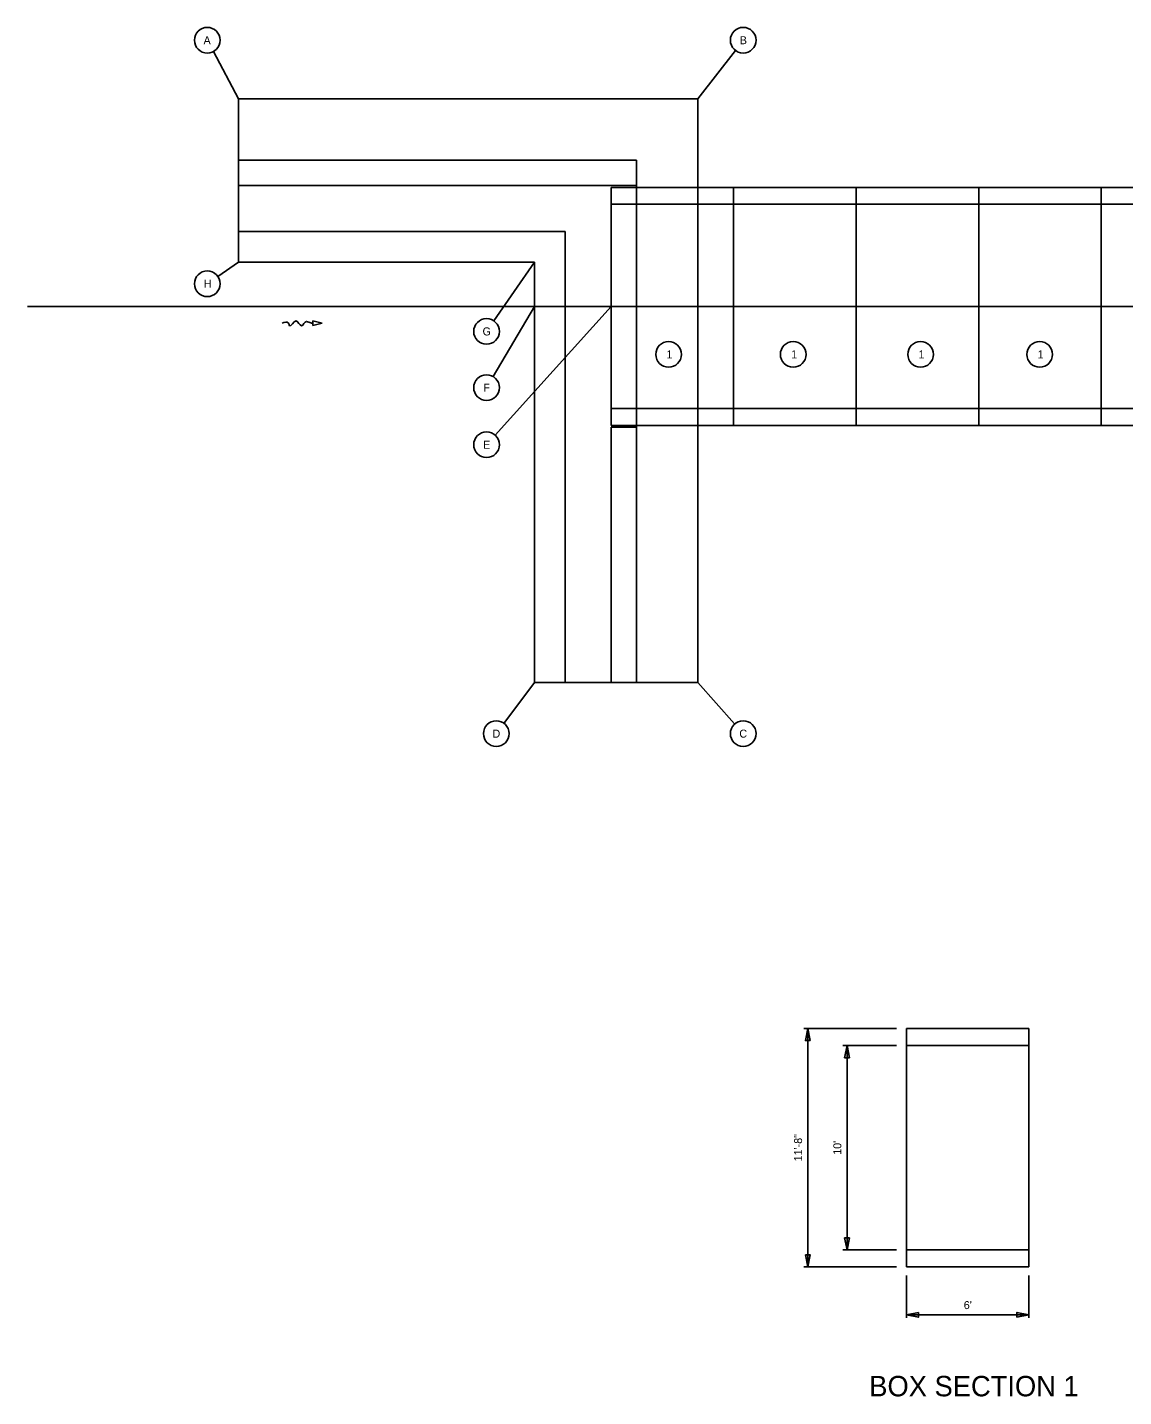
# Model space of a CAD drawing. Extents: x -324 to 238, y 0 to 489.
# Drawn here: x -323.5 to -189.4, y 297.6 to 465.2 of the extents above; entities that cross this region are included whole.
import ezdxf

# ---------------------------------------------------------------- set-up
doc = ezdxf.new("R2010")
doc.units = 0
for name, color, linetype in [('BR_P_Gen_Text', 7, 'Continuous'), ('DR_P_Culvert', 7, 'Continuous'), ('DR_P_Flow_Arrow', 7, 'Continuous'), ('GE_P_Alignment', 7, 'Continuous'), ('SH_Data', 7, 'Continuous'), ('TX_P_1', 7, 'Continuous')]:
    doc.layers.add(name, color=color, linetype=linetype)

msp = doc.modelspace()

# ---------------------------------------------------------------- linework, layer by layer
at = {"layer": 'BR_P_Gen_Text'}
for points in [[(-227.74, 341.17), (-228.33, 341.17), (-228.03, 342.64)], [(-222.94, 339.08), (-223.53, 339.08), (-223.23, 340.55)], [(-223.53, 317.02), (-222.94, 317.02), (-223.23, 315.55)], [(-228.33, 314.94), (-227.74, 314.94), (-228.03, 313.47)], [(-214.49, 307.9), (-214.49, 307.31), (-215.96, 307.6)], [(-202.43, 307.31), (-202.43, 307.9), (-200.96, 307.6)]]:
    msp.add_lwpolyline(points, close=True, dxfattribs=at)
at = {"layer": 'DR_P_Culvert'}
for p, q in [((-297.73, 436.46), (-297.73, 456.46)), ((-297.73, 456.46), (-241.48, 456.46)), ((-241.48, 456.46), (-241.48, 385.01)), ((-297.73, 448.96), (-248.98, 448.96)), ((-248.98, 416.26), (-248.98, 448.96)), ((-297.73, 445.84), (-252.11, 445.84)), ((-252.11, 445.84), (-248.98, 445.84)), ((-252.11, 416.46), (-252.11, 445.63)), ((-252.11, 445.63), (-94.61, 445.63)), ((-237.11, 416.46), (-237.11, 445.63)), ((-222.11, 416.46), (-222.11, 445.63)), ((-207.11, 416.46), (-207.11, 445.63)), ((-192.11, 416.46), (-192.11, 445.63)), ((-252.11, 443.55), (-94.61, 443.55)), ((-297.73, 440.21), (-257.73, 440.21)), ((-257.73, 440.21), (-257.73, 385.01)), ((-297.73, 436.46), (-261.48, 436.46)), ((-261.48, 436.46), (-261.48, 385.01)), ((-252.11, 418.55), (-94.61, 418.55)), ((-252.11, 416.46), (-94.61, 416.46)), ((-252.11, 416.26), (-248.98, 416.26)), ((-252.11, 416.26), (-252.11, 385.01)), ((-248.98, 416.26), (-248.98, 385.01)), ((-261.48, 385.01), (-241.48, 385.01)), ((-215.96, 342.64), (-200.96, 342.64)), ((-215.96, 313.47), (-215.96, 342.64)), ((-200.96, 313.47), (-200.96, 342.64)), ((-215.96, 340.55), (-200.96, 340.55)), ((-215.96, 315.55), (-200.96, 315.55)), ((-215.96, 313.47), (-200.96, 313.47))]:
    msp.add_line(p, q, dxfattribs=at)
at = {"layer": 'DR_P_Flow_Arrow'}
for p, q in [((-288.6, 429.3), (-287.48, 429)), ((-288.6, 428.7), (-288.6, 429.3)), ((-287.48, 429), (-288.6, 428.7))]:
    msp.add_line(p, q, dxfattribs=at)
msp.add_spline([(-288.6, 429), (-288.64, 429), (-289.1, 429.11), (-289.39, 429.21), (-289.99, 428.69), (-290.67, 429.27), (-291.45, 428.69), (-291.61, 429), (-292.38, 429)], degree=3, dxfattribs=at)
at = {"layer": 'GE_P_Alignment'}
msp.add_line((-323.55, 431.05), (-41.24, 431.05), dxfattribs=at)
at = {"layer": 'TX_P_1'}
for p, q in [((-300.79, 462.25), (-297.73, 456.46)), ((-236.9, 462.39), (-241.48, 456.46)), ((-300.24, 434.72), (-297.73, 436.46)), ((-266.45, 429.29), (-261.48, 436.46)), ((-266.55, 422.46), (-261.48, 431.05)), ((-266.3, 415.29), (-252.11, 431.05)), ((-265.22, 380.01), (-261.48, 385.01)), ((-236.99, 379.93), (-241.48, 385.01)), ((-217.17, 342.64), (-228.5, 342.64)), ((-228.03, 342.64), (-228.03, 313.47)), ((-217.17, 340.55), (-223.76, 340.55)), ((-223.23, 340.55), (-223.23, 315.55)), ((-217.17, 315.55), (-223.76, 315.55)), ((-217.17, 313.47), (-228.5, 313.47)), ((-215.96, 312.4), (-215.96, 307.25)), ((-200.96, 312.4), (-200.96, 307.25)), ((-215.96, 307.6), (-200.96, 307.6))]:
    msp.add_line(p, q, dxfattribs=at)
for centre in [(-301.53, 463.64), (-235.94, 463.64), (-301.53, 433.82), (-267.35, 427.99), (-245.07, 425.18), (-229.82, 425.18), (-214.23, 425.18), (-199.65, 425.18), (-267.35, 421.11), (-267.35, 414.12), (-266.16, 378.75), (-235.94, 378.75)]:
    msp.add_circle(centre, 1.57, dxfattribs=at)

# ---------------------------------------------------------------- texts
at = {"layer": 'SH_Data'}
msp.add_text('BOX SECTION 1', height=2.5, dxfattribs=at).set_placement((-220.51, 297.62))
at = {"layer": 'TX_P_1'}
for s, p in [('A', (-301.99, 463.15)), ('B', (-236.36, 463.15)), ('H', (-301.97, 433.33)), ('G', (-267.84, 427.5)), ('1', (-245.33, 424.69)), ('1', (-230.07, 424.69)), ('1', (-214.48, 424.69)), ('1', (-199.91, 424.69)), ('F', (-267.74, 420.62)), ('E', (-267.77, 413.63)), ('D', (-266.62, 378.26)), ('C', (-236.41, 378.26)), ("6'", (-208.94, 308.3))]:
    msp.add_text(s, height=0.98, dxfattribs=at).set_placement(p)
for s, p in [('11\'-8"', (-228.73, 326.39)), ("10'", (-223.93, 327.19))]:
    msp.add_text(s, height=0.98, rotation=90, dxfattribs=at).set_placement(p)

doc.saveas('drawing.dxf')
